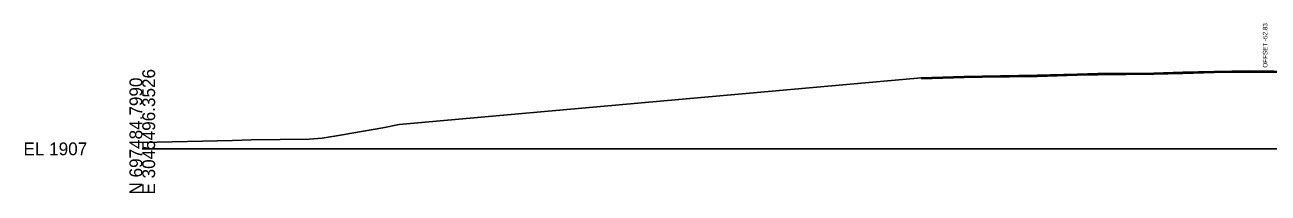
# Model space of a CAD drawing. Extents: x 1574 to 14903, y 7971 to 16537.
# Drawn here: x 4474.3 to 4746.3, y 9990.3 to 10027.1 of the extents above; entities that cross this region are included whole.
import ezdxf

# ---------------------------------------------------------------- set-up
doc = ezdxf.new("R2010")
doc.units = 0
for name, color, linetype in [('DESIGN - SCRATCH - User 1', 7, 'Continuous'), ('DESIGN - SHEET - Light Grid', 7, 'Continuous'), ('SURVEY - GROUND - Bottom of Topsoil Layer', 7, 'Continuous'), ('SURVEY - GROUND - Top of Ground', 7, 'Continuous')]:
    doc.layers.add(name, color=color, linetype=linetype)

msp = doc.modelspace()

# ---------------------------------------------------------------- linework, layer by layer
at = {"layer": 'DESIGN - SHEET - Light Grid'}
msp.add_line((4500, 10000), (4800, 10000), dxfattribs=at)
at = {"layer": 'SURVEY - GROUND - Bottom of Topsoil Layer'}
msp.add_lwpolyline([(4670.45, 10015.33), (4679.83, 10015.6), (4683.79, 10015.68), (4695.76, 10015.85), (4704.56, 10016.12), (4709.07, 10016.22), (4721.31, 10016.33), (4727.68, 10016.53), (4734.49, 10016.68), (4742.2, 10016.82), (4753.06, 10016.7)], dxfattribs=at)
at = {"layer": 'SURVEY - GROUND - Top of Ground'}
msp.add_line((4556.17, 10005.3), (4670.44, 10015.58), dxfattribs=at)
msp.add_line((4556.17, 10005.3), (4670.44, 10015.58), dxfattribs=at)
for points in [[(4670.44, 10015.58), (4679.82, 10015.85), (4683.79, 10015.93), (4695.76, 10016.1), (4704.56, 10016.37), (4709.07, 10016.47), (4721.31, 10016.58), (4727.68, 10016.78), (4734.48, 10016.93), (4742.2, 10017.07), (4753.06, 10016.95)], [(4670.44, 10015.58), (4679.82, 10015.85), (4683.79, 10015.93), (4695.76, 10016.1), (4704.56, 10016.37), (4709.07, 10016.47), (4721.31, 10016.58), (4727.68, 10016.78), (4734.48, 10016.93), (4742.2, 10017.07), (4753.06, 10016.95)], [(4500, 10001.41), (4519.75, 10001.85), (4523.84, 10001.95), (4536.53, 10002.09), (4539.34, 10002.34), (4543.83, 10003.09), (4545.83, 10003.41), (4552.64, 10004.63), (4556.17, 10005.3)], [(4500, 10001.41), (4519.75, 10001.85), (4523.84, 10001.95), (4536.53, 10002.09), (4539.34, 10002.34), (4543.83, 10003.09), (4545.83, 10003.41), (4552.64, 10004.63), (4556.17, 10005.3)]]:
    msp.add_lwpolyline(points, dxfattribs=at)

# ---------------------------------------------------------------- texts
at = {"layer": 'DESIGN - SCRATCH - User 1'}
msp.add_text('OFFSET -52.83', height=1, rotation=90, dxfattribs=at).set_placement((4746.17, 10017.77))
at = {"layer": 'DESIGN - SHEET - Light Grid'}
for s, p in [('E 3045496.3526', (4502.8, 9990)), ('N 697484.7990', (4500, 9990))]:
    msp.add_text(s, height=2.8, rotation=90, dxfattribs=at).set_placement(p)
msp.add_text('EL 1907', height=2.8, dxfattribs=at).set_placement((4474, 9998.6))

doc.saveas('drawing.dxf')
